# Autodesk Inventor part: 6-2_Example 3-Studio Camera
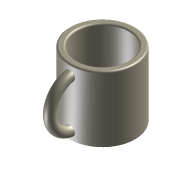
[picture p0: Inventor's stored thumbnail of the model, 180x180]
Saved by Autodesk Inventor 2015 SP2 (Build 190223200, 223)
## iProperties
Created: 2020-09
Part Number: 6-2_Example 3-Studio Camera
Material: 一般
Document SubType Name: Modeling
Designer: 徐冠倫
Mass: 2802.01 g
Surface Area: 2947.51 cm^2
Volume: 2802.01 cm^3
Density: 1 g/cm^3
Appearance: 預設
Author: 徐冠倫
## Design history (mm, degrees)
node "Cup.sat1"
body "Solid1"
node "Base1"
